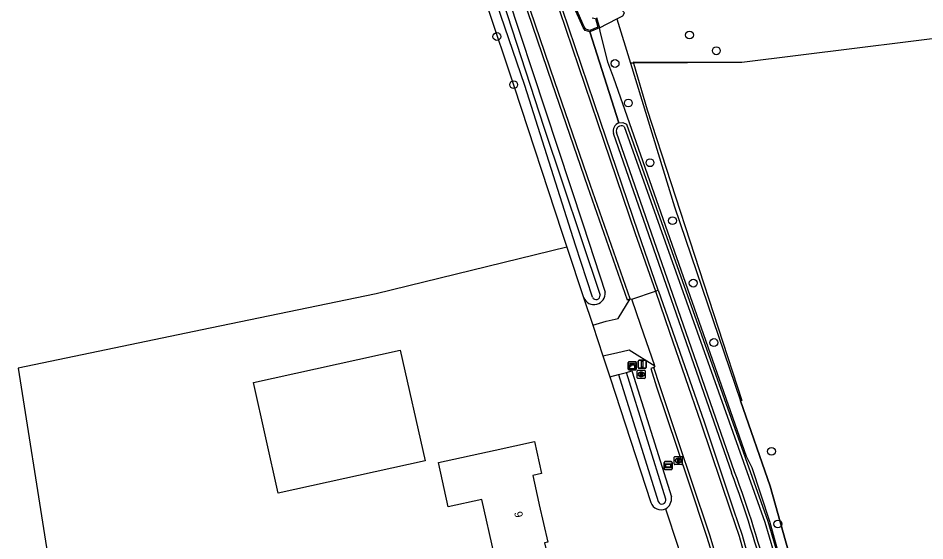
# Model space of a CAD drawing. Extents: x 162515 to 163909, y 388494 to 389773.
# Drawn here: x 163217.2 to 163330.1, y 389109.1 to 389174.2 of the extents above; entities that cross this region are included whole.
import ezdxf

# ---------------------------------------------------------------- set-up
doc = ezdxf.new("R2010")
doc.units = 0
for name, color, linetype in [('IMGEO_Afsluitpaal', 7, 'Continuous'), ('IMGEO_Boom', 7, 'Continuous'), ('IMGEO_Brandkraan', 7, 'Continuous'), ('IMGEO_Duiker', 7, 'Continuous'), ('IMGEO_Erf', 7, 'Continuous'), ('IMGEO_Grasland_agrarisch', 7, 'Continuous'), ('IMGEO_Grasland_overig', 7, 'Continuous'), ('IMGEO_Groenvoorziening', 7, 'Continuous'), ('IMGEO_Hek', 7, 'Continuous'), ('IMGEO_Kast', 7, 'Continuous'), ('IMGEO_Loofbos', 7, 'Continuous'), ('IMGEO_Pand', 7, 'Continuous'), ('IMGEO_Pand_nummerreeks', 7, 'Continuous'), ('IMGEO_Rijbaan_lokaal_gesloten', 7, 'Continuous'), ('IMGEO_Rijbaan_lokaal_halfverhard', 7, 'Continuous'), ('IMGEO_Rijbaan_lokaal_open', 7, 'Continuous'), ('IMGEO_Rioolput', 7, 'Continuous'), ('IMGEO_Verklikker', 7, 'Continuous'), ('IMGEO_Waterloop', 7, 'Continuous')]:
    doc.layers.add(name, color=color, linetype=linetype)

msp = doc.modelspace()

# ---------------------------------------------------------------- linework, layer by layer
at = {"layer": 'IMGEO_Afsluitpaal'}
for p, q in [((163294.44, 389130.66), (163294.44, 389131.46)), ((163294.44, 389131.46), (163294.44, 389130.66)), ((163294.54, 389131.56), (163295.33, 389131.56)), ((163295.33, 389131.56), (163294.54, 389131.56)), ((163295.43, 389131.46), (163295.43, 389130.66)), ((163295.43, 389130.66), (163295.43, 389131.46)), ((163295.33, 389130.56), (163294.54, 389130.56)), ((163294.54, 389130.56), (163295.33, 389130.56))]:
    msp.add_line(p, q, dxfattribs=at)
msp.add_lwpolyline([(163294.86, 389131.43), (163295.01, 389131.43), (163295.01, 389130.68), (163294.86, 389130.68), (163294.86, 389131.43)], dxfattribs=at)
for centre, start, end in [((163294.54, 389131.46), 90, 180), ((163294.54, 389131.46), 90, 180), ((163295.33, 389131.46), 0, 90), ((163295.33, 389131.46), 360, 90), ((163294.54, 389130.66), 180, 270), ((163294.54, 389130.66), 180, 270), ((163295.33, 389130.66), 270, 0), ((163295.33, 389130.66), 270, 0)]:
    msp.add_arc(centre, 0.1, start, end, dxfattribs=at)
at = {"layer": 'IMGEO_Boom'}
for centre in [(163276.83, 389171.89), (163300.82, 389172.08), (163304.16, 389170.12), (163291.55, 389168.53), (163278.92, 389165.89), (163293.21, 389163.61), (163295.9, 389156.17), (163298.7, 389148.95), (163301.29, 389141.17), (163303.86, 389133.76), (163311.04, 389120.21), (163311.82, 389111.16)]:
    msp.add_circle(centre, 0.489, dxfattribs=at)
at = {"layer": 'IMGEO_Brandkraan'}
for p, q in [((163298.93, 389118.64), (163298.93, 389119.49)), ((163299.01, 389119.56), (163299.86, 389119.56)), ((163299.86, 389118.56), (163299.01, 389118.56)), ((163299.42, 389119.34), (163299.45, 389119.34)), ((163299.44, 389118.78), (163299.42, 389118.78)), ((163299.93, 389119.49), (163299.93, 389118.64))]:
    msp.add_line(p, q, dxfattribs=at)
for points in [[(163298.93, 389118.64), (163298.93, 389119.49)], [(163299.01, 389119.56), (163299.86, 389119.56)], [(163299.86, 389118.56), (163299.01, 389118.56)], [(163299.28, 389119.26), (163299.28, 389118.86), (163299.49, 389118.86)], [(163299.51, 389119.26), (163299.28, 389119.26)], [(163299.46, 389119.18), (163299.4, 389119.18), (163299.4, 389119.1)], [(163299.4, 389119.1), (163299.46, 389119.1)], [(163299.47, 389119.03), (163299.4, 389119.03), (163299.4, 389118.95)], [(163299.4, 389118.95), (163299.47, 389118.95)], [(163299.93, 389119.49), (163299.93, 389118.64)]]:
    msp.add_lwpolyline(points, dxfattribs=at)
for centre, radius, start, end in [((163299.01, 389119.49), 0.0765, 91.552, 178.448), ((163299.01, 389119.49), 0.0765, 91.552, 178.448), ((163299.01, 389118.64), 0.0765, 181.552, 268.448), ((163299.01, 389118.64), 0.0765, 181.552, 268.448), ((163299.46, 389119.14), 0.0379, 267.8285, 90.9355), ((163299.47, 389118.99), 0.0404, 269.8759, 90.5077), ((163299.5, 389119.11), 0.251, 268.6676, 293.5347), ((163299.52, 389119.12), 0.145, 59.4692, 91.5367), ((163299.54, 389119.16), 0.0922, 285.5137, 58.1501), ((163299.54, 389118.97), 0.105, 301.3115, 78.989), ((163299.86, 389119.49), 0.0765, 1.552, 88.448), ((163299.86, 389119.49), 0.0765, 1.552, 88.448), ((163299.86, 389118.64), 0.0765, 271.552, 358.448), ((163299.86, 389118.64), 0.0765, 271.552, 358.448)]:
    msp.add_arc(centre, radius, start, end, dxfattribs=at)
for centre, major_axis, ratio, start_param, end_param in [((163299.42, 389119.06), (-0.387, 0.002), 0.722429, 4.712389, 7.853982), ((163299.44, 389119.06), (-0.39, 0.002), 0.717154, 1.570796, 4.712389)]:
    msp.add_ellipse(centre, major_axis=major_axis, ratio=ratio, start_param=start_param, end_param=end_param, dxfattribs=at)
at = {"layer": 'IMGEO_Duiker'}
msp.add_lwpolyline([(163288.41, 389172.46), (163292.02, 389161.13)], dxfattribs=at)
at = {"layer": 'IMGEO_Erf'}
for points in [[(163285.54, 389145.63), (163287.62, 389139.39)], [(163290.9, 389129.51), (163290.94, 389129.38), (163295.99, 389113.82)]]:
    msp.add_lwpolyline(points, dxfattribs=at)
msp.add_arc((163297.3, 389114.34), 1.41, 201.6231, 292.1671, dxfattribs=at)
at = {"layer": 'IMGEO_Grasland_agrarisch'}
for points in [[(163258.84, 389232.54), (163261.63, 389219.11), (163268.64, 389196.56), (163278.98, 389165.63), (163284.91, 389147.53), (163285.54, 389145.63)], [(163307.36, 389168.67), (163293.81, 389168.69), (163293.84, 389168.59)], [(163293.84, 389168.59), (163295.53, 389162.77), (163307.35, 389126.56), (163307.16, 389126.5)], [(163285.54, 389145.63), (163261.78, 389139.83), (163241.1, 389135.56), (163217.2, 389130.56), (163224.26, 389085.9), (163224.4, 389084.98)]]:
    msp.add_lwpolyline(points, dxfattribs=at)
at = {"layer": 'IMGEO_Grasland_overig'}
for points in [[(163288.41, 389172.46), (163287.83, 389172.65), (163287.56, 389173), (163286.66, 389175.04), (163279.44, 389196.74), (163273.49, 389216.24), (163271.85, 389222.4), (163270.74, 389226.12), (163269.44, 389231.24), (163268.41, 389236.27), (163267.22, 389245.04), (163266.9, 389250), (163266.89, 389253.1), (163267.49, 389260.25), (163267.99, 389262.94), (163269.93, 389269.01), (163270.56, 389269.29), (163270.58, 389268.68)], [(163261.94, 389233.21), (163264.65, 389219.44), (163273.43, 389191.33), (163287.58, 389148.42), (163290.32, 389140.06)], [(163312.33, 389106.03), (163310.82, 389111.46), (163308.65, 389118.16), (163307.93, 389119.58), (163291.38, 389166.69), (163290.67, 389168.7), (163289.7, 389172.58), (163289.6, 389172.96)], [(163292.02, 389161.13), (163288.41, 389172.46)], [(163293.48, 389168.59), (163298.96, 389150.69), (163307.16, 389126.5)], [(163306.08, 389117.55), (163291.36, 389159.82)], [(163287.62, 389139.39), (163288.77, 389135.91)], [(163307.16, 389126.5), (163310.88, 389115.86), (163314.09, 389104.33), (163316.99, 389092.13), (163318.51, 389073.31), (163367.52, 389078.3), (163374.79, 389079.28)]]:
    msp.add_lwpolyline(points, dxfattribs=at)
for centre, radius, start, end in [((163292.34, 389160.15), 1.03, 107.8328, 198.5842), ((163288.93, 389139.89), 1.4, 201.2048, 6.7579), ((163166.83, 389065.93), 148.5, 9.0628, 20.3401)]:
    msp.add_arc(centre, radius, start, end, dxfattribs=at)
at = {"layer": 'IMGEO_Groenvoorziening'}
for points in [[(163289.6, 389172.96), (163288.41, 389172.46)], [(163292.02, 389161.13), (163292.52, 389161.17), (163292.98, 389160.96), (163310.56, 389111.5), (163312.21, 389105.99)]]:
    msp.add_lwpolyline(points, dxfattribs=at)
at = {"layer": 'IMGEO_Hek'}
for points in [[(163291.79, 389174.11), (163293.48, 389168.59), (163298.96, 389150.69), (163307.16, 389126.5)], [(163386.48, 389080.86), (163374.79, 389079.28), (163367.52, 389078.3), (163318.51, 389073.31), (163316.99, 389092.13), (163314.09, 389104.33), (163310.88, 389115.86), (163307.16, 389126.5)]]:
    msp.add_lwpolyline(points, dxfattribs=at)
at = {"layer": 'IMGEO_Kast'}
for p, q in [((163293.2, 389130.44), (163293.2, 389131.28)), ((163293.2, 389131.28), (163293.2, 389130.44)), ((163293.27, 389131.37), (163294.11, 389131.37)), ((163294.11, 389131.37), (163293.27, 389131.37)), ((163294.2, 389131.29), (163294.2, 389130.45)), ((163294.2, 389130.45), (163294.2, 389131.29)), ((163294.12, 389130.37), (163293.28, 389130.37)), ((163293.28, 389130.37), (163294.12, 389130.37))]:
    msp.add_line(p, q, dxfattribs=at)
for points in [[(163293.39, 389131.16), (163293.99, 389131.16), (163293.99, 389131.07), (163293.39, 389131.07), (163293.39, 389131.16)], [(163293.39, 389130.98), (163293.99, 389130.98), (163293.99, 389130.49), (163293.39, 389130.49), (163293.39, 389130.98)]]:
    msp.add_lwpolyline(points, dxfattribs=at)
msp.add_circle((163293.48, 389130.83), 0.0377, dxfattribs=at)
for centre, start, end in [((163293.28, 389131.29), 92.4484, 184.2845), ((163293.28, 389131.29), 92.4484, 184.2845), ((163294.12, 389131.29), 2.4484, 94.2845), ((163294.12, 389131.29), 2.4484, 94.2845), ((163293.28, 389130.45), 182.4484, 274.2845), ((163293.28, 389130.45), 182.4484, 274.2845), ((163294.12, 389130.45), 272.4484, 4.2845), ((163294.12, 389130.45), 272.4484, 4.2845)]:
    msp.add_arc(centre, 0.0779, start, end, dxfattribs=at)
at = {"layer": 'IMGEO_Loofbos'}
for points in [[(163291.79, 389174.11), (163293.48, 389168.59)], [(163374.79, 389079.28), (163366.65, 389123.96), (163359.92, 389160.85), (163356.4, 389163.04), (163342.1, 389172.97), (163307.36, 389168.67)], [(163293.84, 389168.59), (163293.48, 389168.59)], [(163307.36, 389168.67), (163293.84, 389168.59)], [(163290.03, 389132.12), (163290.9, 389129.51)], [(163292.96, 389130.04), (163293.64, 389130.22), (163293.68, 389130.11), (163298.58, 389114.54)], [(163290.9, 389129.51), (163291.99, 389129.79)], [(163297.84, 389113.03), (163299.36, 389108.41), (163299.51, 389107.92), (163299.75, 389107.17)]]:
    msp.add_lwpolyline(points, dxfattribs=at)
msp.add_arc((163297.05, 389114.35), 1.54, 300.7033, 7.0208, dxfattribs=at)
at = {"layer": 'IMGEO_Pand'}
for points in [[(163249.6, 389114.98), (163246.5, 389128.77), (163264.8, 389132.82), (163267.89, 389119.03), (163249.6, 389114.98)], [(163269.54, 389118.8), (163276.62, 389120.37), (163281.51, 389121.45), (163282.39, 389117.44), (163281.3, 389117.2), (163282.06, 389113.74), (163282.1, 389113.55), (163283.16, 389108.9), (163282.76, 389108.79), (163282.96, 389107.93), (163278.84, 389107.02), (163278.66, 389107.86), (163276.51, 389107.39), (163274.97, 389114.21), (163270.77, 389113.28), (163269.54, 389118.8)]]:
    msp.add_lwpolyline(points, dxfattribs=at)
at = {"layer": 'IMGEO_Rijbaan_lokaal_gesloten'}
for points in [[(163293.42, 389139.21), (163288.49, 389153.34), (163284.06, 389166.25), (163280.39, 389177.02), (163277.41, 389185.71), (163273.32, 389198.2), (163271.69, 389203.62), (163268.49, 389214.13), (163266.96, 389218.85), (163266.48, 389220.61), (163265.83, 389222.99), (163263.78, 389231.09), (163262.86, 389235.54)], [(163269.17, 389223.93), (163270.14, 389220.49), (163272.1, 389214.24), (163274.17, 389207.71), (163276.21, 389201.09), (163278.85, 389192.65), (163282.44, 389181.73), (163284.64, 389175.15), (163289.36, 389161.2), (163294.07, 389147.37), (163296.57, 389140.16)], [(163293.62, 389139.16), (163293.62, 389139.16), (163296.57, 389140.16)], [(163296.57, 389140.16), (163298.33, 389135.05), (163302.25, 389123.75), (163305.93, 389112.78), (163306.99, 389109.63), (163307.53, 389107.7), (163308.36, 389104.8), (163309.38, 389101.1)], [(163293.42, 389139.21), (163293.61, 389139.17), (163293.62, 389139.16)], [(163296.51, 389130.87), (163294.76, 389135.9), (163293.62, 389139.16)], [(163296.51, 389130.87), (163296.4, 389130.64)], [(163304.84, 389104.83), (163303.34, 389109.77), (163301.08, 389116.56), (163299.6, 389120.88), (163297.11, 389128.39), (163296.4, 389130.64)]]:
    msp.add_lwpolyline(points, dxfattribs=at)
at = {"layer": 'IMGEO_Rijbaan_lokaal_halfverhard'}
for points in [[(163262.46, 389235.46), (163263.39, 389230.99), (163265.44, 389222.88), (163266.09, 389220.5), (163266.58, 389218.73), (163268.11, 389214.02), (163271.3, 389203.51), (163272.94, 389198.07), (163277.03, 389185.58), (163280.01, 389176.89), (163283.68, 389166.12), (163288.11, 389153.21), (163293.04, 389139.08), (163293.42, 389139.21)], [(163296.94, 389140.29), (163294.44, 389147.5), (163289.74, 389161.32), (163285.01, 389175.27), (163282.82, 389181.85), (163279.23, 389192.78), (163276.6, 389201.21), (163274.56, 389207.83), (163272.48, 389214.36), (163270.52, 389220.61), (163269.59, 389223.92)], [(163296.57, 389140.16), (163296.94, 389140.29)], [(163296.94, 389140.29), (163298.71, 389135.19), (163302.63, 389123.88), (163306.31, 389112.91), (163307.37, 389109.75), (163307.92, 389107.81), (163308.74, 389104.91), (163309.77, 389101.2)], [(163296.4, 389130.64), (163296.02, 389130.52), (163296.73, 389128.26), (163299.23, 389120.74), (163300.7, 389116.43), (163302.96, 389109.64), (163304.46, 389104.72)]]:
    msp.add_lwpolyline(points, dxfattribs=at)
at = {"layer": 'IMGEO_Rijbaan_lokaal_open'}
for points in [[(163288.77, 389135.91), (163290.45, 389136.42), (163291.92, 389136.77), (163293.42, 389139.21)], [(163288.77, 389135.91), (163290.03, 389132.12)], [(163290.03, 389132.12), (163291.73, 389132.49), (163293.32, 389132.86), (163296.51, 389130.87)]]:
    msp.add_lwpolyline(points, dxfattribs=at)
at = {"layer": 'IMGEO_Rioolput'}
for p, q in [((163294.31, 389129.38), (163294.31, 389130.23)), ((163294.38, 389130.31), (163295.23, 389130.31)), ((163294.79, 389130.08), (163294.82, 389130.08)), ((163295.31, 389130.23), (163295.31, 389129.38)), ((163295.23, 389129.3), (163294.38, 389129.3)), ((163294.82, 389129.53), (163294.79, 389129.53))]:
    msp.add_line(p, q, dxfattribs=at)
for points in [[(163294.31, 389129.38), (163294.31, 389130.23)], [(163294.38, 389130.31), (163295.23, 389130.31)], [(163294.9, 389130), (163294.64, 389130), (163294.64, 389129.6)], [(163294.82, 389129.92), (163294.77, 389129.92), (163294.77, 389129.84)], [(163294.77, 389129.84), (163294.82, 389129.84)], [(163295.31, 389130.23), (163295.31, 389129.38)], [(163295.23, 389129.3), (163294.38, 389129.3)], [(163294.64, 389129.6), (163294.77, 389129.6), (163294.77, 389129.77), (163294.78, 389129.77)], [(163294.82, 389129.74), (163294.9, 389129.6), (163295.04, 389129.6), (163294.97, 389129.73)]]:
    msp.add_lwpolyline(points, dxfattribs=at)
for centre, radius, start, end in [((163294.38, 389130.23), 0.0765, 91.552, 178.448), ((163294.38, 389130.23), 0.0765, 91.552, 178.448), ((163294.83, 389129.83), 0.0964, 77.0061, 93.1865), ((163294.8, 389130.03), 0.19, 274.7715, 282.9687), ((163294.84, 389129.88), 0.0378, 276.6634, 79.6772), ((163294.89, 389129.89), 0.109, 350.3612, 89.416), ((163294.89, 389129.89), 0.112, 277.5842, 350.9817), ((163295.23, 389130.23), 0.0765, 1.552, 88.448), ((163295.23, 389130.23), 0.0765, 1.552, 88.448), ((163294.38, 389129.38), 0.0765, 181.552, 268.448), ((163294.38, 389129.38), 0.0765, 181.552, 268.448), ((163294.78, 389129.71), 0.0533, 26.0293, 88.6989), ((163294.88, 389129.68), 0.108, 29.5134, 73.7905), ((163295.23, 389129.38), 0.0765, 271.552, 358.448), ((163295.23, 389129.38), 0.0765, 271.552, 358.448)]:
    msp.add_arc(centre, radius, start, end, dxfattribs=at)
for centre, major_axis, ratio, start_param, end_param in [((163294.79, 389129.8), (-0.387, 0.002), 0.722429, 4.712389, 7.853982), ((163294.82, 389129.8), (-0.39, 0.002), 0.717154, 1.570796, 4.712389)]:
    msp.add_ellipse(centre, major_axis=major_axis, ratio=ratio, start_param=start_param, end_param=end_param, dxfattribs=at)
at = {"layer": 'IMGEO_Verklikker'}
for p, q in [((163297.67, 389118.03), (163297.67, 389118.83)), ((163297.67, 389118.83), (163297.67, 389118.03)), ((163297.77, 389118.93), (163298.56, 389118.93)), ((163298.56, 389118.93), (163297.77, 389118.93)), ((163298.66, 389118.83), (163298.66, 389118.03)), ((163298.66, 389118.03), (163298.66, 389118.83)), ((163298.56, 389117.93), (163297.77, 389117.93)), ((163297.77, 389117.93), (163298.56, 389117.93))]:
    msp.add_line(p, q, dxfattribs=at)
for points in [[(163297.77, 389118.66), (163298.56, 389118.66), (163298.56, 389118.19), (163297.77, 389118.19), (163297.77, 389118.66)], [(163297.83, 389118.59), (163297.83, 389118.26), (163298.49, 389118.26), (163298.49, 389118.59), (163297.83, 389118.59)]]:
    msp.add_lwpolyline(points, dxfattribs=at)
for centre, start, end in [((163297.77, 389118.83), 90, 180), ((163297.77, 389118.83), 90, 180), ((163298.56, 389118.83), 0, 90), ((163298.56, 389118.83), 360, 90), ((163297.77, 389118.03), 180, 270), ((163297.77, 389118.03), 180, 270), ((163298.56, 389118.03), 270, 0), ((163298.56, 389118.03), 270, 0)]:
    msp.add_arc(centre, 0.1, start, end, dxfattribs=at)
at = {"layer": 'IMGEO_Waterloop'}
for points in [[(163280.3, 389165.8), (163274.39, 389183.15), (163267.32, 389204.95), (163262.78, 389219.16), (163261.29, 389226.41), (163260.05, 389232.7)], [(163261.27, 389232.91), (163263.69, 389219.26), (163267.13, 389209.19), (163272, 389194.09), (163275.3, 389183.38), (163282.67, 389160.59), (163289.68, 389139.68)], [(163288.7, 389174.22), (163289.1, 389174.12), (163289.4, 389173.05), (163288.4, 389172.64), (163287.93, 389172.79), (163287.7, 389173.09), (163286.82, 389175.1)], [(163291.79, 389174.11), (163292.18, 389174.32), (163292.5, 389174.48), (163292.73, 389174.84), (163292.25, 389175.35)], [(163289.23, 389174.26), (163289.6, 389172.96)], [(163289.6, 389172.96), (163291.79, 389174.11)], [(163288.73, 389139.41), (163286.62, 389145.89), (163280.3, 389165.8)], [(163292.67, 389160.68), (163310.2, 389111.38), (163311.83, 389105.89)], [(163306.44, 389117.67), (163291.73, 389159.93)], [(163291.99, 389129.79), (163292.96, 389130.04)], [(163297.87, 389114.27), (163292.96, 389130.04)], [(163291.99, 389129.79), (163296.94, 389113.96)]]:
    msp.add_lwpolyline(points, dxfattribs=at)
for centre, radius, start, end in [((163292.33, 389160.15), 0.632, 57.1299, 199.9955), ((163289.18, 389139.62), 0.501, 205.7041, 6.4733), ((163166.76, 389065.91), 148.96, 9.0607, 20.3348), ((163297.4, 389114.12), 0.488, 199.0918, 18.3353)]:
    msp.add_arc(centre, radius, start, end, dxfattribs=at)

# ---------------------------------------------------------------- texts
at = {"layer": 'IMGEO_Pand_nummerreeks'}
msp.add_text('9', height=1, rotation=282.6662, dxfattribs=at).set_placement((163278.97, 389112.6))

doc.saveas('drawing.dxf')
